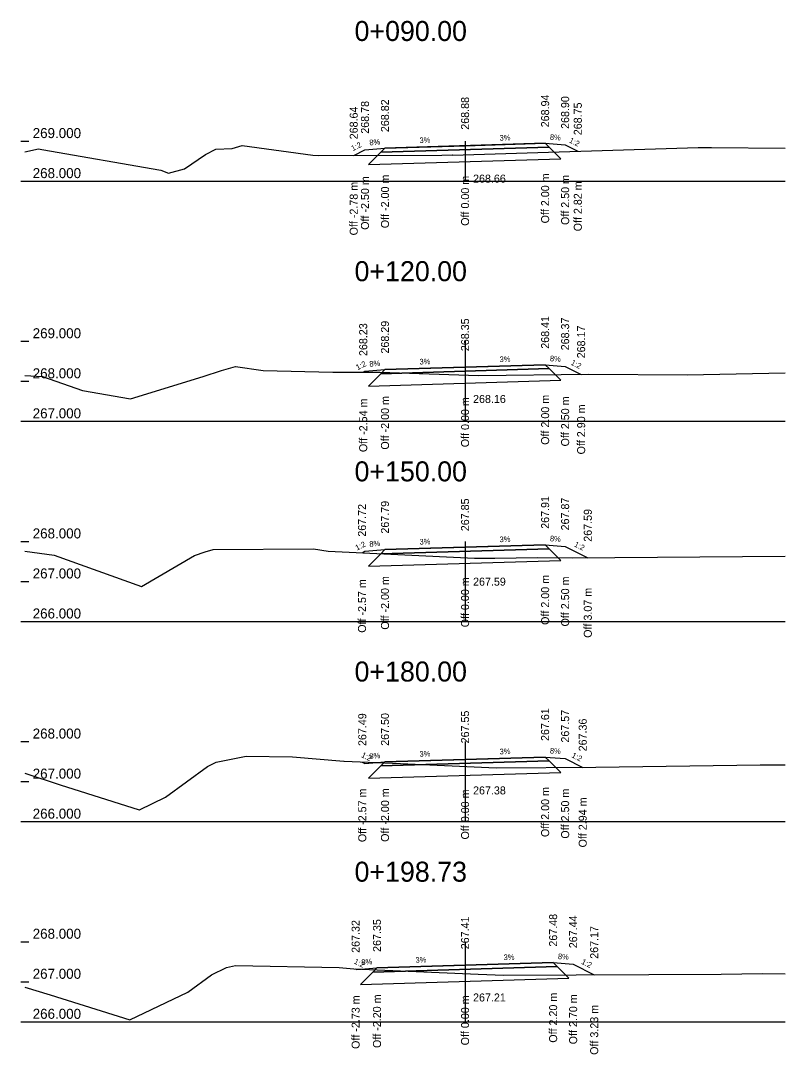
# Model space of a CAD drawing. Extents: x -550605 to -538780, y -1102367 to -1093705.
# Drawn here: x -541373.9 to -541354.8, y -1098198.36 to -1098172.55 of the extents above; entities that cross this region are included whole.
import ezdxf

# ---------------------------------------------------------------- set-up
doc = ezdxf.new("R2010")
doc.units = 0
for name, color, linetype in [('PŘ - offsety od osy', 7, 'Continuous'), ('PŘ - popis', 7, 'Continuous'), ('PŘ - příčné sklony', 7, 'Continuous'), ('PŘ - terén', 7, 'Continuous'), ('PŘ - vozovka', 7, 'Continuous'), ('PŘ - výšky offsetů', 7, 'Continuous')]:
    doc.layers.add(name, color=color, linetype=linetype)

msp = doc.modelspace()

# ---------------------------------------------------------------- linework, layer by layer
at = {"layer": 'PŘ - popis'}
for p, q in [((-541373.898, -1098175.553), (-541373.698, -1098175.553)), ((-541362.798, -1098175.553), (-541362.798, -1098176.553)), ((-541373.898, -1098176.553), (-541373.698, -1098176.553)), ((-541373.798, -1098176.553), (-541354.798, -1098176.553)), ((-541373.898, -1098180.553), (-541373.698, -1098180.553)), ((-541362.798, -1098180.553), (-541362.798, -1098182.553)), ((-541373.898, -1098181.553), (-541373.698, -1098181.553)), ((-541373.898, -1098182.553), (-541373.698, -1098182.553)), ((-541373.798, -1098182.553), (-541354.798, -1098182.553)), ((-541373.898, -1098185.553), (-541373.698, -1098185.553)), ((-541362.798, -1098185.553), (-541362.798, -1098187.553)), ((-541373.898, -1098186.553), (-541373.698, -1098186.553)), ((-541373.898, -1098187.553), (-541373.698, -1098187.553)), ((-541373.798, -1098187.553), (-541354.798, -1098187.553)), ((-541373.898, -1098190.553), (-541373.698, -1098190.553)), ((-541362.798, -1098190.553), (-541362.798, -1098192.553)), ((-541373.898, -1098191.553), (-541373.698, -1098191.553)), ((-541373.898, -1098192.553), (-541373.698, -1098192.553)), ((-541373.798, -1098192.553), (-541354.798, -1098192.553)), ((-541373.898, -1098195.553), (-541373.698, -1098195.553)), ((-541362.798, -1098195.553), (-541362.798, -1098197.553)), ((-541373.898, -1098196.553), (-541373.698, -1098196.553)), ((-541373.898, -1098197.553), (-541373.698, -1098197.553)), ((-541373.798, -1098197.553), (-541354.798, -1098197.553))]:
    msp.add_line(p, q, dxfattribs=at)
at = {"layer": 'PŘ - terén'}
for points in [[(-541373.798, -1098175.823), (-541373.451, -1098175.749), (-541373.371, -1098175.76), (-541373.369, -1098175.76), (-541370.399, -1098176.281), (-541370.206, -1098176.353), (-541370.206, -1098176.353), (-541369.808, -1098176.247), (-541369.282, -1098175.889), (-541369.022, -1098175.752), (-541368.618, -1098175.737), (-541368.617, -1098175.737), (-541368.366, -1098175.666), (-541366.604, -1098175.902), (-541366.471, -1098175.911), (-541366.466, -1098175.911), (-541366.466, -1098175.911), (-541363.381, -1098175.905), (-541363.116, -1098175.9), (-541363.116, -1098175.9), (-541363.114, -1098175.901), (-541356.979, -1098175.717), (-541356.646, -1098175.717), (-541354.798, -1098175.732)], [(-541373.798, -1098181.408), (-541373.353, -1098181.433), (-541373.351, -1098181.433), (-541372.352, -1098181.783), (-541371.153, -1098181.995), (-541371.153, -1098181.995), (-541369.339, -1098181.436), (-541368.884, -1098181.283), (-541368.535, -1098181.18), (-541367.838, -1098181.284), (-541366.098, -1098181.322), (-541364.927, -1098181.322), (-541362.465, -1098181.407), (-541359.704, -1098181.378), (-541357.253, -1098181.39), (-541354.798, -1098181.344)], [(-541373.798, -1098185.798), (-541373.06, -1098185.895), (-541370.878, -1098186.682), (-541369.56, -1098185.903), (-541369.559, -1098185.903), (-541369.29, -1098185.812), (-541369.093, -1098185.754), (-541366.585, -1098185.741), (-541366.219, -1098185.794), (-541366.218, -1098185.795), (-541362.566, -1098185.97), (-541362.05, -1098185.969), (-541362.05, -1098185.969), (-541360.991, -1098185.958), (-541360.125, -1098185.964), (-541354.798, -1098185.918)], [(-541373.798, -1098191.345), (-541372.913, -1098191.631), (-541372.913, -1098191.631), (-541370.935, -1098192.255), (-541370.934, -1098192.255), (-541370.282, -1098191.944), (-541369.23, -1098191.176), (-541369.017, -1098191.07), (-541368.269, -1098190.914), (-541368.269, -1098190.914), (-541367.107, -1098190.936), (-541365.823, -1098191.046), (-541365.822, -1098191.045), (-541365.821, -1098191.045), (-541364.412, -1098191.104), (-541362.025, -1098191.205), (-541362.024, -1098191.205), (-541362.024, -1098191.205), (-541359.535, -1098191.196), (-541355.424, -1098191.134), (-541354.798, -1098191.136)], [(-541373.798, -1098196.685), (-541373.159, -1098196.878), (-541371.173, -1098197.504), (-541371.173, -1098197.504), (-541369.721, -1098196.811), (-541369.133, -1098196.382), (-541368.759, -1098196.196), (-541368.53, -1098196.148), (-541368.53, -1098196.149), (-541365.944, -1098196.198), (-541365.578, -1098196.229), (-541365.575, -1098196.228), (-541365.575, -1098196.228), (-541362.473, -1098196.359), (-541361.83, -1098196.386), (-541361.83, -1098196.386), (-541361.829, -1098196.386), (-541356.399, -1098196.366), (-541355.367, -1098196.35), (-541354.798, -1098196.352)]]:
    msp.add_lwpolyline(points, dxfattribs=at)
at = {"layer": 'PŘ - vozovka'}
for points in [[(-541365.579, -1098175.909), (-541365.298, -1098175.769), (-541364.798, -1098175.729), (-541362.798, -1098175.669), (-541360.798, -1098175.609), (-541360.298, -1098175.649), (-541359.982, -1098175.807)], [(-541365.342, -1098181.322), (-541365.298, -1098181.3), (-541364.798, -1098181.26), (-541362.798, -1098181.2), (-541360.798, -1098181.14), (-541360.298, -1098181.18), (-541359.898, -1098181.38)], [(-541365.372, -1098185.835), (-541365.298, -1098185.798), (-541364.798, -1098185.758), (-541362.798, -1098185.698), (-541360.798, -1098185.638), (-541360.298, -1098185.678), (-541359.732, -1098185.961)], [(-541365.365, -1098191.064), (-541365.298, -1098191.098), (-541364.798, -1098191.058), (-541362.798, -1098190.998), (-541360.798, -1098190.938), (-541360.298, -1098190.978), (-541359.859, -1098191.197)], [(-541365.531, -1098196.23), (-541365.498, -1098196.247), (-541364.998, -1098196.207), (-541362.798, -1098196.141), (-541360.598, -1098196.075), (-541360.098, -1098196.115), (-541359.572, -1098196.378)]]:
    msp.add_lwpolyline(points, dxfattribs=at)
for points in [[(-541364.898, -1098175.832), (-541365.211, -1098176.141), (-541360.409, -1098175.997), (-541360.698, -1098175.706)], [(-541364.798, -1098175.729), (-541364.898, -1098175.832), (-541360.698, -1098175.706), (-541360.798, -1098175.609)], [(-541364.798, -1098181.26), (-541364.898, -1098181.363), (-541360.698, -1098181.237), (-541360.798, -1098181.14)], [(-541364.898, -1098181.363), (-541365.211, -1098181.673), (-541360.409, -1098181.529), (-541360.698, -1098181.237)], [(-541364.898, -1098185.861), (-541365.211, -1098186.171), (-541360.409, -1098186.027), (-541360.698, -1098185.735)], [(-541364.798, -1098185.758), (-541364.898, -1098185.861), (-541360.698, -1098185.735), (-541360.798, -1098185.638)], [(-541364.798, -1098191.058), (-541364.898, -1098191.161), (-541360.698, -1098191.035), (-541360.798, -1098190.938)], [(-541364.898, -1098191.161), (-541365.211, -1098191.47), (-541360.409, -1098191.326), (-541360.698, -1098191.035)], [(-541365.098, -1098196.31), (-541365.411, -1098196.619), (-541360.209, -1098196.463), (-541360.498, -1098196.172)], [(-541364.998, -1098196.207), (-541365.098, -1098196.31), (-541360.498, -1098196.172), (-541360.598, -1098196.075)]]:
    msp.add_lwpolyline(points, close=True, dxfattribs=at)

# ---------------------------------------------------------------- texts
at = {"layer": 'PŘ - offsety od osy'}
for s, p in [('Off -2.50 m', (-541365.198, -1098177.769)), ('Off -2.00 m', (-541364.698, -1098177.729)), ('Off 0.00 m', (-541362.698, -1098177.669)), ('Off 2.00 m', (-541360.698, -1098177.609)), ('Off 2.50 m', (-541360.198, -1098177.649)), ('Off -2.78 m', (-541365.479, -1098177.909)), ('Off 2.82 m', (-541359.882, -1098177.807)), ('Off -2.00 m', (-541364.698, -1098183.26)), ('Off 0.00 m', (-541362.698, -1098183.2)), ('Off 2.00 m', (-541360.698, -1098183.14)), ('Off 2.50 m', (-541360.198, -1098183.18)), ('Off -2.54 m', (-541365.242, -1098183.322)), ('Off 2.90 m', (-541359.798, -1098183.38)), ('Off -2.57 m', (-541365.272, -1098187.835)), ('Off -2.00 m', (-541364.698, -1098187.758)), ('Off 0.00 m', (-541362.698, -1098187.698)), ('Off 2.00 m', (-541360.698, -1098187.638)), ('Off 2.50 m', (-541360.198, -1098187.678)), ('Off 3.07 m', (-541359.632, -1098187.961)), ('Off -2.57 m', (-541365.265, -1098193.064)), ('Off -2.00 m', (-541364.698, -1098193.058)), ('Off 0.00 m', (-541362.698, -1098192.998)), ('Off 2.00 m', (-541360.698, -1098192.938)), ('Off 2.50 m', (-541360.198, -1098192.978)), ('Off 2.94 m', (-541359.759, -1098193.197)), ('Off -2.73 m', (-541365.431, -1098198.23)), ('Off -2.20 m', (-541364.898, -1098198.207)), ('Off 0.00 m', (-541362.698, -1098198.141)), ('Off 2.20 m', (-541360.498, -1098198.075)), ('Off 2.70 m', (-541359.998, -1098198.115)), ('Off 3.23 m', (-541359.472, -1098198.378))]:
    msp.add_text(s, height=0.2, rotation=90, dxfattribs=at).set_placement(p)
at = {"layer": 'PŘ - popis'}
for s, height, p in [('0+090.00', 0.5, (-541365.558, -1098173.053)), ('269.000', 0.25, (-541373.598, -1098175.478)), ('268.000', 0.25, (-541373.598, -1098176.478)), ('0+120.00', 0.5, (-541365.558, -1098179.053)), ('269.000', 0.25, (-541373.598, -1098180.478)), ('268.000', 0.25, (-541373.598, -1098181.478)), ('267.000', 0.25, (-541373.598, -1098182.478)), ('0+150.00', 0.5, (-541365.558, -1098184.053)), ('268.000', 0.25, (-541373.598, -1098185.478)), ('267.000', 0.25, (-541373.598, -1098186.478)), ('266.000', 0.25, (-541373.598, -1098187.478)), ('0+180.00', 0.5, (-541365.558, -1098189.053)), ('268.000', 0.25, (-541373.598, -1098190.478)), ('267.000', 0.25, (-541373.598, -1098191.478)), ('266.000', 0.25, (-541373.598, -1098192.478)), ('0+198.73', 0.5, (-541365.558, -1098194.053)), ('268.000', 0.25, (-541373.598, -1098195.478)), ('267.000', 0.25, (-541373.598, -1098196.478)), ('266.000', 0.25, (-541373.598, -1098197.478))]:
    msp.add_text(s, height=height, dxfattribs=at).set_placement(p)
at = {"layer": 'PŘ - příčné sklony'}
for s, rotation, p in [('8%', 4.5739, (-541365.183, -1098175.66)), ('3%', 1.7184, (-541363.933, -1098175.603)), ('3%', 1.7184, (-541361.933, -1098175.543)), ('8%', 355.4261, (-541360.683, -1098175.518)), ('1:2', 333.4349, (-541360.212, -1098175.58)), ('1:2', 26.5651, (-541365.6, -1098175.808)), ('3%', 1.7184, (-541361.933, -1098181.074)), ('8%', 355.4261, (-541360.683, -1098181.049)), ('1:2', 26.5651, (-541365.482, -1098181.28)), ('8%', 4.5739, (-541365.183, -1098181.191)), ('3%', 1.7184, (-541363.933, -1098181.134)), ('1:2', 333.4349, (-541360.17, -1098181.132)), ('1:2', 26.5651, (-541365.497, -1098185.786)), ('8%', 4.5739, (-541365.183, -1098185.689)), ('3%', 1.7184, (-541363.933, -1098185.632)), ('3%', 1.7184, (-541361.933, -1098185.572)), ('8%', 355.4261, (-541360.683, -1098185.547)), ('1:2', 333.4349, (-541360.087, -1098185.672)), ('3%', 1.7184, (-541361.933, -1098190.872)), ('8%', 355.4261, (-541360.683, -1098190.847)), ('1:2', 333.4349, (-541365.404, -1098190.933)), ('8%', 4.5739, (-541365.183, -1098190.988)), ('3%', 1.7184, (-541363.933, -1098190.932)), ('1:2', 333.4349, (-541360.15, -1098190.94)), ('3%', 1.7184, (-541361.833, -1098196.012)), ('8%', 355.4261, (-541360.483, -1098195.984)), ('1:2', 333.4349, (-541365.587, -1098196.09)), ('8%', 4.5739, (-541365.383, -1098196.137)), ('3%', 1.7184, (-541364.033, -1098196.078)), ('1:2', 333.4349, (-541359.907, -1098196.098))]:
    msp.add_text(s, height=0.14, rotation=rotation, dxfattribs=at).set_placement(p)
at = {"layer": 'PŘ - výšky offsetů'}
for s, p in [('268.88', (-541362.698, -1098175.269)), ('268.94', (-541360.698, -1098175.209)), ('268.90', (-541360.198, -1098175.249)), ('268.64', (-541365.479, -1098175.509)), ('268.78', (-541365.198, -1098175.369)), ('268.82', (-541364.698, -1098175.329)), ('268.75', (-541359.882, -1098175.407)), ('268.23', (-541365.242, -1098180.922)), ('268.29', (-541364.698, -1098180.86)), ('268.35', (-541362.698, -1098180.8)), ('268.41', (-541360.698, -1098180.74)), ('268.37', (-541360.198, -1098180.78)), ('268.17', (-541359.798, -1098180.98)), ('267.79', (-541364.698, -1098185.358)), ('267.85', (-541362.698, -1098185.298)), ('267.91', (-541360.698, -1098185.238)), ('267.87', (-541360.198, -1098185.278)), ('267.72', (-541365.272, -1098185.435)), ('267.59', (-541359.632, -1098185.561)), ('267.49', (-541365.265, -1098190.664)), ('267.50', (-541364.698, -1098190.658)), ('267.55', (-541362.698, -1098190.598)), ('267.61', (-541360.698, -1098190.538)), ('267.57', (-541360.198, -1098190.578)), ('267.36', (-541359.759, -1098190.797)), ('267.48', (-541360.498, -1098195.675)), ('267.32', (-541365.431, -1098195.83)), ('267.35', (-541364.898, -1098195.807)), ('267.41', (-541362.698, -1098195.741)), ('267.44', (-541359.998, -1098195.715)), ('267.17', (-541359.472, -1098195.978))]:
    msp.add_text(s, height=0.2, rotation=90, dxfattribs=at).set_placement(p)
for s, p in [('268.66', (-541362.598, -1098176.591)), ('268.16', (-541362.598, -1098182.095)), ('267.59', (-541362.598, -1098186.658)), ('267.38', (-541362.598, -1098191.873)), ('267.21', (-541362.598, -1098197.045))]:
    msp.add_text(s, height=0.2, dxfattribs=at).set_placement(p)

doc.saveas('drawing.dxf')
